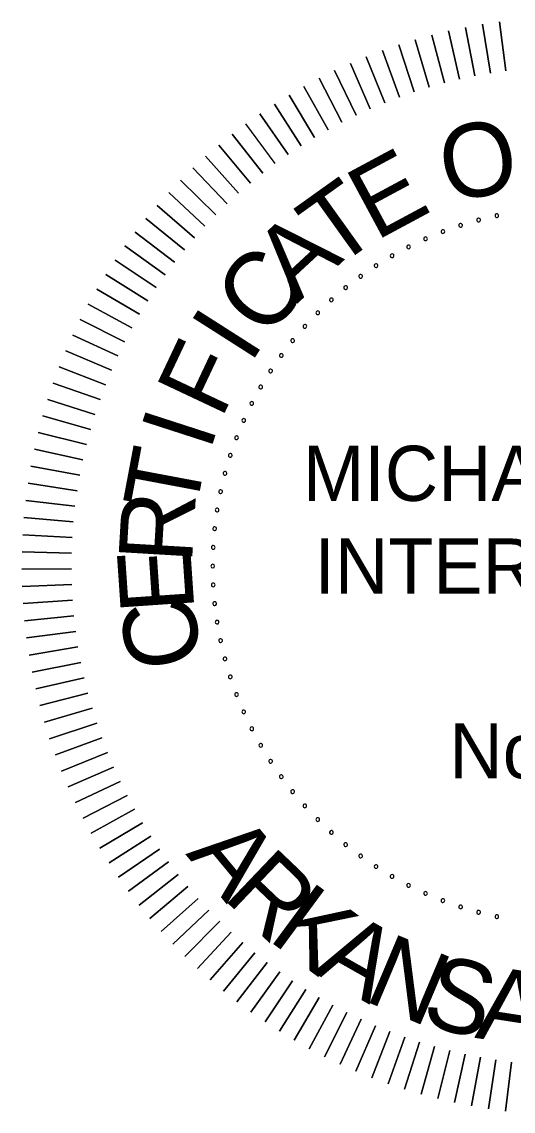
# Model space of a CAD drawing. Extents: x -35254 to 17396, y -8913 to 11592.
# Drawn here: x 5412 to 6524, y -5964 to -3494 of the extents above; entities that cross this region are included whole.
import ezdxf

# ---------------------------------------------------------------- set-up
doc = ezdxf.new("R2010")
doc.units = 0
doc.layers.add('G-ANNO-TEXT', color=7, linetype='Continuous')

msp = doc.modelspace()

# ---------------------------------------------------------------- linework, layer by layer
at = {"layer": 'G-ANNO-TEXT'}
for points in [[(6472.7, -3610.9), (6454.5, -3500.1)], [(6454.5, -3500.1), (6472.7, -3610.9)], [(6507.9, -3605.6), (6493.2, -3494.4)], [(6493.2, -3494.4), (6507.9, -3605.6)], [(6368.4, -3633.1), (6339.9, -3524.5)], [(6339.9, -3524.5), (6368.4, -3633.1)], [(6402.9, -3624.6), (6377.8, -3515.2)], [(6377.8, -3515.2), (6402.9, -3624.6)], [(6437.7, -3617.2), (6416.1, -3507)], [(6416.1, -3507), (6437.7, -3617.2)], [(6300.2, -3653.3), (6264.9, -3546.7)], [(6264.9, -3546.7), (6300.2, -3653.3)], [(6334.1, -3642.6), (6302.2, -3535)], [(6302.2, -3535), (6334.1, -3642.6)], [(6233.4, -3677.8), (6191.5, -3573.6)], [(6191.5, -3573.6), (6233.4, -3677.8)], [(6266.6, -3665), (6228, -3559.6)], [(6228, -3559.6), (6266.6, -3665)], [(6200.6, -3691.5), (6155.5, -3588.8)], [(6155.5, -3588.8), (6200.6, -3691.5)], [(6136.4, -3722.2), (6084.9, -3622.5)], [(6084.9, -3622.5), (6136.4, -3722.2)], [(6168.3, -3706.4), (6119.9, -3605.1)], [(6119.9, -3605.1), (6168.3, -3706.4)], [(6105.1, -3739), (6050.5, -3641)], [(6050.5, -3641), (6105.1, -3739)], [(6074.3, -3756.8), (6016.6, -3660.5)], [(6016.6, -3660.5), (6074.3, -3756.8)], [(6014.5, -3795.2), (5950.9, -3702.8)], [(5950.9, -3702.8), (6014.5, -3795.2)], [(6044.1, -3775.6), (5983.4, -3681.1)], [(5983.4, -3681.1), (6044.1, -3775.6)], [(5985.5, -3815.9), (5919, -3725.4)], [(5957.1, -3837.4), (5887.9, -3749.1)], [(5887.9, -3749.1), (5957.1, -3837.4)], [(5929.5, -3859.8), (5857.5, -3773.7)], [(5857.5, -3773.7), (5929.5, -3859.8)], [(5902.6, -3883), (5827.9, -3799.2)], [(5827.9, -3799.2), (5902.6, -3883)], [(5876.4, -3907.1), (5799.1, -3825.7)], [(5799.1, -3825.7), (5876.4, -3907.1)], [(5851, -3932), (5771.2, -3853.1)], [(5771.2, -3853.1), (5851, -3932)], [(5826.4, -3957.7), (5744.2, -3881.3)], [(5744.2, -3881.3), (5826.4, -3957.7)], [(5802.6, -3984.1), (5718, -3910.4)], [(5718, -3910.4), (5802.6, -3984.1)], [(5779.7, -4011.3), (5692.8, -3940.2)], [(5692.8, -3940.2), (5779.7, -4011.3)], [(5757.6, -4039.2), (5668.5, -3970.9)], [(5668.5, -3970.9), (5757.6, -4039.2)], [(5736.4, -4067.7), (5645.2, -4002.3)], [(5645.2, -4002.3), (5736.4, -4067.7)], [(5716.1, -4096.9), (5622.9, -4034.4)], [(5622.9, -4034.4), (5716.1, -4096.9)], [(5696.7, -4126.8), (5601.7, -4067.2)], [(5601.7, -4067.2), (5696.7, -4126.8)], [(5678.3, -4157.2), (5581.4, -4100.6)], [(5581.4, -4100.6), (5678.3, -4157.2)], [(5660.9, -4188.2), (5562.2, -4134.7)], [(5562.2, -4134.7), (5660.9, -4188.2)], [(5644.4, -4219.7), (5544.1, -4169.3)], [(5544.1, -4169.3), (5644.4, -4219.7)], [(5628.9, -4251.7), (5527.1, -4204.5)], [(5527.1, -4204.5), (5628.9, -4251.7)], [(5614.5, -4284.2), (5511.2, -4240.3)], [(5511.2, -4240.3), (5614.5, -4284.2)], [(5601.1, -4317.2), (5496.5, -4276.5)], [(5496.5, -4276.5), (5601.1, -4317.2)], [(5588.7, -4350.5), (5482.9, -4313.1)], [(5482.9, -4313.1), (5588.7, -4350.5)], [(5577.3, -4384.2), (5470.4, -4350.2)], [(5470.4, -4350.2), (5577.3, -4384.2)], [(5567.1, -4418.3), (5459.1, -4387.6)], [(5459.1, -4387.6), (5567.1, -4418.3)], [(5557.9, -4452.6), (5449, -4425.3)], [(5449, -4425.3), (5557.9, -4452.6)], [(5549.8, -4487.3), (5440.1, -4463.4)], [(5440.1, -4463.4), (5549.8, -4487.3)], [(5542.7, -4522.1), (5432.4, -4501.7)], [(5432.4, -4501.7), (5542.7, -4522.1)], [(5536.8, -4557.2), (5425.9, -4540.3)], [(5425.9, -4540.3), (5536.8, -4557.2)], [(5532, -4592.5), (5420.6, -4579)], [(5420.6, -4579), (5532, -4592.5)], [(5528.3, -4627.8), (5416.5, -4617.9)], [(5416.5, -4617.9), (5528.3, -4627.8)], [(5525.7, -4663.3), (5413.7, -4656.9)], [(5413.7, -4656.9), (5525.7, -4663.3)], [(5524.2, -4698.8), (5412.1, -4695.9)], [(5412.1, -4695.9), (5524.2, -4698.8)], [(5523.9, -4734.4), (5411.7, -4735)], [(5411.7, -4735), (5523.9, -4734.4)], [(5524.6, -4770), (5412.5, -4774.1)], [(5412.5, -4774.1), (5524.6, -4770)], [(5526.5, -4805.5), (5414.5, -4813.2)], [(5414.5, -4813.2), (5526.5, -4805.5)], [(5529.5, -4840.9), (5417.8, -4852.1)], [(5417.8, -4852.1), (5529.5, -4840.9)], [(5533.6, -4876.3), (5422.3, -4890.9)], [(5422.3, -4890.9), (5533.6, -4876.3)], [(5538.8, -4911.4), (5428.1, -4929.6)], [(5428.1, -4929.6), (5538.8, -4911.4)], [(5545.1, -4946.4), (5435, -4968.1)], [(5435, -4968.1), (5545.1, -4946.4)], [(5552.5, -4981.2), (5443.1, -5006.3)], [(5443.1, -5006.3), (5552.5, -4981.2)], [(5561, -5015.8), (5452.5, -5044.3)], [(5452.5, -5044.3), (5561, -5015.8)], [(5570.6, -5050), (5463, -5081.9)], [(5463, -5081.9), (5570.6, -5050)], [(5581.2, -5084), (5474.7, -5119.2)], [(5474.7, -5119.2), (5581.2, -5084)], [(5592.9, -5117.5), (5487.6, -5156.1)], [(5487.6, -5156.1), (5592.9, -5117.5)], [(5605.7, -5150.7), (5501.6, -5192.6)], [(5501.6, -5192.6), (5605.7, -5150.7)], [(5619.5, -5183.5), (5516.8, -5228.7)], [(5516.8, -5228.7), (5619.5, -5183.5)], [(5634.3, -5215.9), (5533, -5264.2)], [(5533, -5264.2), (5634.3, -5215.9)], [(5650.1, -5247.7), (5550.4, -5299.2)], [(5550.4, -5299.2), (5650.1, -5247.7)], [(5667, -5279.1), (5568.9, -5333.7)], [(5568.9, -5333.7), (5667, -5279.1)], [(5684.8, -5309.8), (5588.5, -5367.5)], [(5588.5, -5367.5), (5684.8, -5309.8)], [(5703.5, -5340.1), (5609.1, -5400.7)], [(5609.1, -5400.7), (5703.5, -5340.1)], [(5723.2, -5369.7), (5630.7, -5433.3)], [(5630.7, -5433.3), (5723.2, -5369.7)], [(5743.8, -5398.7), (5653.4, -5465.1)], [(5653.4, -5465.1), (5743.8, -5398.7)], [(5765.3, -5427), (5677, -5496.3)], [(5677, -5496.3), (5765.3, -5427)], [(5787.7, -5454.6), (5701.6, -5526.6)], [(5701.6, -5526.6), (5787.7, -5454.6)], [(5811, -5481.5), (5727.2, -5556.2)], [(5727.2, -5556.2), (5811, -5481.5)], [(5835.1, -5507.7), (5753.7, -5585)], [(5753.7, -5585), (5835.1, -5507.7)], [(5859.9, -5533.1), (5781, -5612.9)], [(5781, -5612.9), (5859.9, -5533.1)], [(5885.6, -5557.7), (5809.3, -5640)], [(5809.3, -5640), (5885.6, -5557.7)], [(5838.3, -5666.1), (5912.1, -5581.5)], [(5912.1, -5581.5), (5838.3, -5666.1)], [(5868.2, -5691.3), (5939.2, -5604.5)], [(5939.2, -5604.5), (5868.2, -5691.3)], [(5898.8, -5715.6), (5967.1, -5626.6)], [(5967.1, -5626.6), (5898.8, -5715.6)], [(5930.2, -5738.9), (5995.7, -5647.7)], [(5995.7, -5647.7), (5930.2, -5738.9)], [(5962.3, -5761.2), (6024.9, -5668)], [(6024.9, -5668), (5962.3, -5761.2)], [(5995.1, -5782.5), (6054.7, -5687.4)], [(6054.7, -5687.4), (5995.1, -5782.5)], [(6028.6, -5802.7), (6085.2, -5705.8)], [(6085.2, -5705.8), (6028.6, -5802.7)], [(6062.6, -5821.9), (6116.1, -5723.3)], [(6116.1, -5723.3), (6062.6, -5821.9)], [(6097.3, -5840), (6147.7, -5739.7)], [(6147.7, -5739.7), (6097.3, -5840)], [(6132.5, -5857), (6179.7, -5755.2)], [(6179.7, -5755.2), (6132.5, -5857)], [(6168.2, -5872.9), (6212.2, -5769.7)], [(6212.2, -5769.7), (6168.2, -5872.9)], [(6204.4, -5887.7), (6245.1, -5783.1)], [(6245.1, -5783.1), (6204.4, -5887.7)], [(6241, -5901.3), (6278.5, -5795.5)], [(6278.5, -5795.5), (6241, -5901.3)], [(6278.1, -5913.7), (6312.2, -5806.8)], [(6312.2, -5806.8), (6278.1, -5913.7)], [(6315.5, -5925), (6346.2, -5817.1)], [(6346.2, -5817.1), (6315.5, -5925)], [(6353.3, -5935.1), (6380.6, -5826.3)], [(6380.6, -5826.3), (6353.3, -5935.1)], [(6391.4, -5944), (6415.2, -5834.4)], [(6415.2, -5834.4), (6391.4, -5944)], [(6429.7, -5951.7), (6450.1, -5841.4)], [(6450.1, -5841.4), (6429.7, -5951.7)], [(6468.2, -5958.3), (6485.2, -5847.3)], [(6485.2, -5847.3), (6468.2, -5958.3)], [(6507, -5963.5), (6520.4, -5852.1)], [(6520.4, -5852.1), (6507, -5963.5)]]:
    msp.add_lwpolyline(points, dxfattribs=at)
for centre, start, end in [((6445.8, -3943.6), 15, 195), ((6445.8, -3943.6), 195, 15), ((6487.2, -3933.7), 12, 192), ((6487.2, -3933.7), 192, 12), ((6365, -3969.9), 21, 201), ((6365, -3969.9), 201, 21), ((6405.1, -3955.7), 18, 198), ((6405.1, -3955.7), 198, 18), ((6325.7, -3986.2), 24, 204), ((6325.7, -3986.2), 204, 24), ((6250, -4024.8), 30, 210), ((6250, -4024.8), 210, 30), ((6287.3, -4004.5), 27, 207), ((6287.3, -4004.5), 207, 27), ((6213.7, -4047), 33, 213), ((6213.7, -4047), 213, 33), ((6178.7, -4071.1), 36, 216), ((6178.7, -4071.1), 216, 36), ((6144.9, -4096.9), 39, 219), ((6144.9, -4096.9), 219, 39), ((6112.6, -4124.6), 42, 222), ((6112.6, -4124.6), 222, 42), ((6081.8, -4153.8), 45, 225), ((6081.8, -4153.8), 225, 45), ((6052.5, -4184.7), 48, 228), ((6052.5, -4184.7), 228, 48), ((6024.9, -4217), 51, 231), ((6024.9, -4217), 231, 51), ((5999, -4250.7), 54, 234), ((5999, -4250.7), 234, 54), ((5974.9, -4285.8), 57, 237), ((5974.9, -4285.8), 237, 57), ((5952.7, -4322), 60, 240), ((5952.7, -4322), 240, 60), ((5932.4, -4359.4), 63, 243), ((5932.4, -4359.4), 243, 63), ((5914.1, -4397.8), 66, 246), ((5914.1, -4397.8), 246, 66), ((5897.8, -4437), 69, 249), ((5897.8, -4437), 249, 69), ((5883.6, -4477.1), 72, 252), ((5883.6, -4477.1), 252, 72), ((5871.6, -4517.9), 75, 255), ((5871.6, -4517.9), 255, 75), ((5861.6, -4559.2), 78, 258), ((5861.6, -4559.2), 258, 78), ((5853.9, -4601), 81, 261), ((5853.9, -4601), 261, 81), ((5848.3, -4643.2), 84, 264), ((5848.3, -4643.2), 264, 84), ((5845, -4685.6), 87, 267), ((5845, -4685.6), 267, 87), ((5843.9, -4728.1), 90, 270), ((5843.9, -4728.1), 270, 90), ((5845, -4770.6), 93, 273), ((5845, -4770.6), 273, 93), ((5848.3, -4813), 96, 276), ((5848.3, -4813), 276, 96), ((5853.9, -4855.1), 99, 279), ((5853.9, -4855.1), 279, 99), ((5861.6, -4896.9), 102, 282), ((5861.6, -4896.9), 282, 102), ((5871.6, -4938.3), 105, 285), ((5871.6, -4938.3), 285, 105), ((5883.6, -4979.1), 108, 288), ((5883.6, -4979.1), 288, 108), ((5897.8, -5019.1), 111, 291), ((5897.8, -5019.1), 291, 111), ((5914.1, -5058.4), 114, 294), ((5914.1, -5058.4), 294, 114), ((5932.4, -5096.8), 117, 297), ((5932.4, -5096.8), 297, 117), ((5952.7, -5134.2), 120, 300), ((5952.7, -5134.2), 300, 120), ((5974.9, -5170.4), 123, 303), ((5974.9, -5170.4), 303, 123), ((5999, -5205.5), 126, 306), ((5999, -5205.5), 306, 126), ((6024.9, -5239.2), 129, 309), ((6024.9, -5239.2), 309, 129), ((6052.5, -5271.5), 132, 312), ((6052.5, -5271.5), 312, 132), ((6081.8, -5302.4), 135, 315), ((6081.8, -5302.4), 315, 135), ((6112.6, -5331.6), 138, 318), ((6112.6, -5331.6), 318, 138), ((6144.9, -5359.3), 141, 321), ((6144.9, -5359.3), 321, 141), ((6178.7, -5385.1), 144, 324), ((6178.7, -5385.1), 324, 144), ((6213.7, -5409.2), 147, 327), ((6213.7, -5409.2), 327, 147), ((6250, -5431.4), 150, 330), ((6250, -5431.4), 330, 150), ((6287.3, -5451.7), 153, 333), ((6287.3, -5451.7), 333, 153), ((6325.7, -5470), 156, 336), ((6325.7, -5470), 336, 156), ((6365, -5486.3), 159, 339), ((6365, -5486.3), 339, 159), ((6405.1, -5500.5), 162, 342), ((6405.1, -5500.5), 342, 162), ((6445.8, -5512.6), 165, 345), ((6445.8, -5512.6), 345, 165), ((6487.2, -5522.5), 168, 348), ((6487.2, -5522.5), 348, 168)]:
    msp.add_arc(centre, 4.17, start, end, dxfattribs=at)

# ---------------------------------------------------------------- texts
for s, rotation, p in [('O', 10.7295, (6374.5, -3904.8)), ('E', 28.279, (6212.6, -3992.2)), ('T', 35.5725, (6119.6, -4056.7)), ('A', 42.8659, (6034.9, -4133.7)), ('C', 50.1594, (5964.8, -4217)), ('I', 57.4529, (5928.6, -4272.7)), ('F', 64.7464, (5863.2, -4397.4)), ('I', 72.0398, (5837.4, -4470.6)), ('T', 79.3333, (5804.2, -4614.2)), ('R', 86.6268, (5796.6, -4724.4)), ('E', 93.9203, (5802.7, -4828.5)), ('C', 101.2137, (5824, -4944.4)), ('A', 309.5859, (5781.4, -5380.7)), ('R', 316.3356, (5864.2, -5479)), ('K', 323.6428, (5966.1, -5573.6)), ('A', 330.3925, (6070.3, -5648.9)), ('N', 337.1422, (6182.5, -5711.3)), ('S', 344.4494, (6311.4, -5763.6)), ('A', 351.1991, (6435.5, -5796.9))]:
    msp.add_text(s, height=166.7, rotation=rotation, dxfattribs=at).set_placement(p)
for s, height, p in [('MICHAEL BAKER', 125.016, (6047.8, -4580.3)), (' INTERNATIONAL', 125.016, (6027.7, -4790.5)), (' No. 1126', 125.02, (6333.4, -5209.1))]:
    msp.add_text(s, height=height, dxfattribs=at).set_placement(p)

doc.saveas('drawing.dxf')
